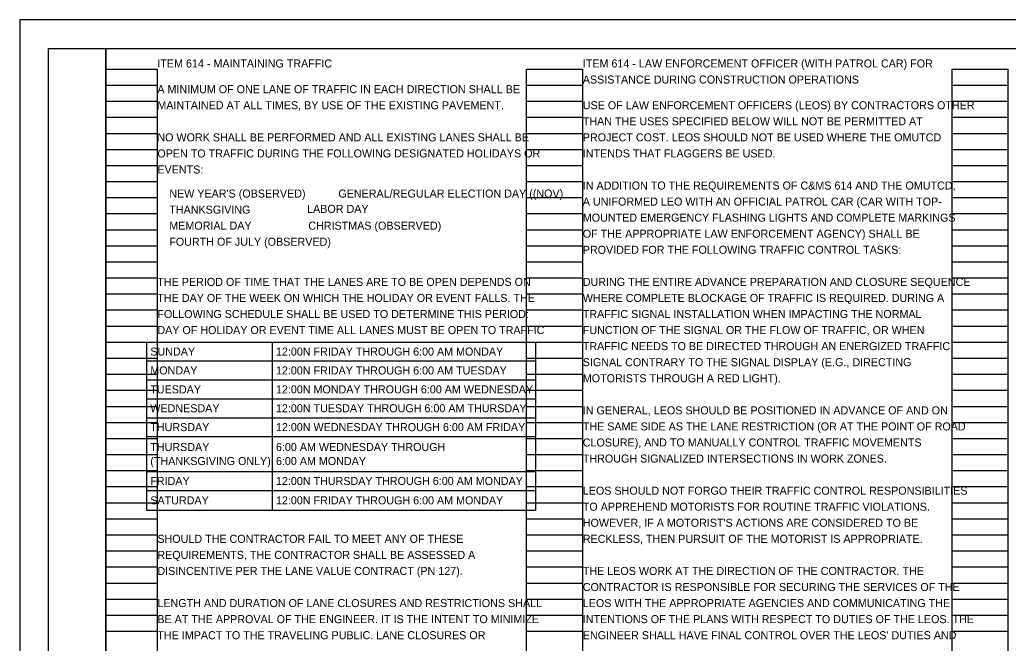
# Model space of a CAD drawing. Extents: x 0 to 34, y 0 to 22.
# Drawn here: x 0 to 17.24, y 11.13 to 22 of the extents above; entities that cross this region are included whole.
import ezdxf

# ---------------------------------------------------------------- set-up
doc = ezdxf.new("R2010")
doc.units = 0
for name, color, linetype in [('SH_Border', 7, 'Continuous'), ('SH_Cut_Line', 7, 'Continuous'), ('SH_Data', 7, 'Continuous'), ('SH_Text', 7, 'Continuous')]:
    doc.layers.add(name, color=color, linetype=linetype)

msp = doc.modelspace()

# ---------------------------------------------------------------- linework, layer by layer
at = {"layer": 'SH_Border'}
for points in [[(0.5, 21.5), (1.5, 21.5), (1.5, 0.5), (0.5, 0.5)], [(1.5, 21.5), (33.5, 21.5), (33.5, 0.5), (1.5, 0.5)]]:
    msp.add_lwpolyline(points, close=True, dxfattribs=at)
at = {"layer": 'SH_Cut_Line'}
msp.add_lwpolyline([(0, 0), (34, 0), (34, 22), (0, 22)], close=True, dxfattribs=at)
at = {"layer": 'SH_Data'}
for p, q in [((1.5, 0.98), (1.5, 21.14)), ((1.5, 21.14), (2.4, 21.14)), ((2.4, 0.98), (2.4, 21.14)), ((8.84, 0.98), (8.84, 21.14)), ((8.84, 21.14), (9.82, 21.14)), ((9.82, 0.98), (9.82, 21.14)), ((16.26, 0.98), (16.26, 21.14)), ((16.26, 21.14), (17.24, 21.14)), ((17.24, 0.98), (17.24, 21.14)), ((1.5, 20.86), (2.4, 20.86)), ((8.84, 20.86), (9.82, 20.86)), ((16.26, 20.86), (17.24, 20.86)), ((1.5, 20.58), (2.4, 20.58)), ((8.84, 20.58), (9.82, 20.58)), ((16.26, 20.58), (17.24, 20.58)), ((1.5, 20.3), (2.4, 20.3)), ((8.84, 20.3), (9.82, 20.3)), ((16.26, 20.3), (17.24, 20.3)), ((1.5, 20.02), (2.4, 20.02)), ((8.84, 20.02), (9.82, 20.02)), ((16.26, 20.02), (17.24, 20.02)), ((1.5, 19.74), (2.4, 19.74)), ((8.84, 19.74), (9.82, 19.74)), ((16.26, 19.74), (17.24, 19.74)), ((1.5, 19.46), (2.4, 19.46)), ((8.84, 19.46), (9.82, 19.46)), ((16.26, 19.46), (17.24, 19.46)), ((1.5, 19.18), (2.4, 19.18)), ((8.84, 19.18), (9.82, 19.18)), ((16.26, 19.18), (17.24, 19.18)), ((1.5, 18.9), (2.4, 18.9)), ((8.84, 18.9), (9.82, 18.9)), ((16.26, 18.9), (17.24, 18.9)), ((1.5, 18.62), (2.4, 18.62)), ((8.84, 18.62), (9.82, 18.62)), ((16.26, 18.62), (17.24, 18.62)), ((1.5, 18.34), (2.4, 18.34)), ((8.84, 18.34), (9.82, 18.34)), ((16.26, 18.34), (17.24, 18.34)), ((1.5, 18.06), (2.4, 18.06)), ((8.84, 18.06), (9.82, 18.06)), ((16.26, 18.06), (17.24, 18.06)), ((1.5, 17.78), (2.4, 17.78)), ((8.84, 17.78), (9.82, 17.78)), ((16.26, 17.78), (17.24, 17.78)), ((1.5, 17.5), (2.4, 17.5)), ((8.84, 17.5), (9.82, 17.5)), ((16.26, 17.5), (17.24, 17.5)), ((1.5, 17.22), (2.4, 17.22)), ((8.84, 17.22), (9.82, 17.22)), ((16.26, 17.22), (17.24, 17.22)), ((1.5, 16.94), (2.4, 16.94)), ((8.84, 16.94), (9.82, 16.94)), ((16.26, 16.94), (17.24, 16.94)), ((1.5, 16.66), (2.4, 16.66)), ((8.84, 16.66), (9.82, 16.66)), ((16.26, 16.66), (17.24, 16.66)), ((1.5, 16.38), (2.4, 16.38)), ((8.84, 16.38), (9.82, 16.38)), ((16.26, 16.38), (17.24, 16.38)), ((1.5, 16.1), (2.4, 16.1)), ((8.84, 16.1), (9.82, 16.1)), ((16.26, 16.1), (17.24, 16.1)), ((1.5, 15.82), (2.4, 15.82)), ((8.84, 15.82), (9.82, 15.82)), ((16.26, 15.82), (17.24, 15.82)), ((1.5, 15.54), (2.4, 15.54)), ((8.84, 15.54), (9.82, 15.54)), ((16.26, 15.54), (17.24, 15.54)), ((1.5, 15.26), (2.4, 15.26)), ((8.84, 15.26), (9.82, 15.26)), ((16.26, 15.26), (17.24, 15.26)), ((1.5, 14.98), (2.4, 14.98)), ((8.84, 14.98), (9.82, 14.98)), ((16.26, 14.98), (17.24, 14.98)), ((1.5, 14.7), (2.4, 14.7)), ((8.84, 14.7), (9.82, 14.7)), ((16.26, 14.7), (17.24, 14.7)), ((1.5, 14.42), (2.4, 14.42)), ((8.84, 14.42), (9.82, 14.42)), ((16.26, 14.42), (17.24, 14.42)), ((1.5, 14.14), (2.4, 14.14)), ((8.84, 14.14), (9.82, 14.14)), ((16.26, 14.14), (17.24, 14.14)), ((1.5, 13.86), (2.4, 13.86)), ((8.84, 13.86), (9.82, 13.86)), ((16.26, 13.86), (17.24, 13.86)), ((1.5, 13.58), (2.4, 13.58)), ((8.84, 13.58), (9.82, 13.58)), ((16.26, 13.58), (17.24, 13.58)), ((1.5, 13.3), (2.4, 13.3)), ((8.84, 13.3), (9.82, 13.3)), ((16.26, 13.3), (17.24, 13.3)), ((1.5, 13.02), (2.4, 13.02)), ((8.84, 13.02), (9.82, 13.02)), ((16.26, 13.02), (17.24, 13.02)), ((1.5, 12.74), (2.4, 12.74)), ((8.84, 12.74), (9.82, 12.74)), ((16.26, 12.74), (17.24, 12.74)), ((1.5, 12.46), (2.4, 12.46)), ((8.84, 12.46), (9.82, 12.46)), ((16.26, 12.46), (17.24, 12.46)), ((1.5, 12.18), (2.4, 12.18)), ((8.84, 12.18), (9.82, 12.18)), ((16.26, 12.18), (17.24, 12.18)), ((1.5, 11.9), (2.4, 11.9)), ((8.84, 11.9), (9.82, 11.9)), ((16.26, 11.9), (17.24, 11.9)), ((1.5, 11.62), (2.4, 11.62)), ((8.84, 11.62), (9.82, 11.62)), ((16.26, 11.62), (17.24, 11.62)), ((1.5, 11.34), (2.4, 11.34)), ((8.84, 11.34), (9.82, 11.34)), ((16.26, 11.34), (17.24, 11.34))]:
    msp.add_line(p, q, dxfattribs=at)
at = {"layer": 'SH_Text'}
for p, q in [((2.211, 16.38), (8.997, 16.38)), ((2.211, 16.38), (2.211, 13.448)), ((4.402, 16.38), (4.402, 13.448)), ((8.997, 16.38), (8.997, 13.448)), ((2.211, 16.051), (8.997, 16.051)), ((2.211, 15.721), (8.997, 15.721)), ((2.211, 15.392), (8.997, 15.392)), ((2.211, 15.062), (8.997, 15.062)), ((2.211, 14.733), (8.997, 14.733)), ((2.211, 14.124), (8.997, 14.124)), ((2.211, 13.794), (8.997, 13.794)), ((2.211, 13.448), (8.997, 13.448))]:
    msp.add_line(p, q, dxfattribs=at)

# ---------------------------------------------------------------- texts
for s, p in [('ITEM 614 - MAINTAINING TRAFFIC', (2.4, 21.168)), ('ITEM 614 - LAW ENFORCEMENT OFFICER (WITH PATROL CAR) FOR ', (9.82, 21.168)), ('A MINIMUM OF ONE LANE OF TRAFFIC IN EACH DIRECTION SHALL BE ', (2.4, 20.72)), ('ASSISTANCE DURING CONSTRUCTION OPERATIONS', (9.82, 20.888)), ('MAINTAINED AT ALL TIMES, BY USE OF THE EXISTING PAVEMENT.', (2.4, 20.44)), ('USE OF LAW ENFORCEMENT OFFICERS (LEOS) BY CONTRACTORS OTHER ', (9.82, 20.44)), ('THAN THE USES SPECIFIED BELOW WILL NOT BE PERMITTED AT ', (9.82, 20.16)), ('NO WORK SHALL BE PERFORMED AND ALL EXISTING LANES SHALL BE ', (2.4, 19.88)), ('PROJECT COST. LEOS SHOULD NOT BE USED WHERE THE OMUTCD ', (9.82, 19.88)), ('OPEN TO TRAFFIC DURING THE FOLLOWING DESIGNATED HOLIDAYS OR ', (2.4, 19.6)), ('INTENDS THAT FLAGGERS BE USED.', (9.82, 19.6)), ('EVENTS:', (2.4, 19.32)), ('IN ADDITION TO THE REQUIREMENTS OF C&MS 614 AND THE OMUTCD, ', (9.82, 19.04)), ("    NEW YEAR'S (OBSERVED)           GENERAL/REGULAR ELECTION DAY ((NOV)", (2.4, 18.9)), ('A UNIFORMED LEO WITH AN OFFICIAL PATROL CAR (CAR WITH TOP-', (9.82, 18.76)), ('    THANKSGIVING', (2.4, 18.62)), ('    LABOR DAY', (4.804, 18.633)), ('MOUNTED EMERGENCY FLASHING LIGHTS AND COMPLETE MARKINGS ', (9.82, 18.48)), ('    MEMORIAL DAY                   CHRISTMAS (OBSERVED)', (2.4, 18.34)), ('OF THE APPROPRIATE LAW ENFORCEMENT AGENCY) SHALL BE ', (9.82, 18.2)), ('    FOURTH OF JULY (OBSERVED) ', (2.4, 18.06)), ('PROVIDED FOR THE FOLLOWING TRAFFIC CONTROL TASKS:', (9.82, 17.92)), ('THE PERIOD OF TIME THAT THE LANES ARE TO BE OPEN DEPENDS ON ', (2.4, 17.36)), ('DURING THE ENTIRE ADVANCE PREPARATION AND CLOSURE SEQUENCE ', (9.82, 17.36)), ('THE DAY OF THE WEEK ON WHICH THE HOLIDAY OR EVENT FALLS. THE ', (2.4, 17.08)), ('WHERE COMPLETE BLOCKAGE OF TRAFFIC IS REQUIRED. DURING A ', (9.82, 17.08)), ('FOLLOWING SCHEDULE SHALL BE USED TO DETERMINE THIS PERIOD:', (2.4, 16.8)), ('TRAFFIC SIGNAL INSTALLATION WHEN IMPACTING THE NORMAL ', (9.82, 16.8)), ('DAY OF HOLIDAY OR EVENT TIME ALL LANES MUST BE OPEN TO TRAFFIC', (2.4, 16.52)), ('FUNCTION OF THE SIGNAL OR THE FLOW OF TRAFFIC, OR WHEN ', (9.82, 16.52)), ('TRAFFIC NEEDS TO BE DIRECTED THROUGH AN ENERGIZED TRAFFIC ', (9.82, 16.24)), ('SUNDAY', (2.277, 16.145)), ('12:00N FRIDAY THROUGH 6:00 AM MONDAY', (4.468, 16.145)), ('SIGNAL CONTRARY TO THE SIGNAL DISPLAY (E.G., DIRECTING ', (9.82, 15.96)), ('MONDAY', (2.277, 15.816)), ('12:00N FRIDAY THROUGH 6:00 AM TUESDAY', (4.468, 15.816)), ('MOTORISTS THROUGH A RED LIGHT).', (9.82, 15.68)), ('TUESDAY', (2.277, 15.486)), ('12:00N MONDAY THROUGH 6:00 AM WEDNESDAY', (4.468, 15.486)), ('WEDNESDAY', (2.277, 15.157)), ('12:00N TUESDAY THROUGH 6:00 AM THURSDAY', (4.468, 15.157)), ('IN GENERAL, LEOS SHOULD BE POSITIONED IN ADVANCE OF AND ON ', (9.82, 15.12)), ('THURSDAY', (2.277, 14.828)), ('12:00N WEDNESDAY THROUGH 6:00 AM FRIDAY', (4.468, 14.828)), ('THE SAME SIDE AS THE LANE RESTRICTION (OR AT THE POINT OF ROAD ', (9.82, 14.84)), ('CLOSURE), AND TO MANUALLY CONTROL TRAFFIC MOVEMENTS ', (9.82, 14.56)), ('THURSDAY', (2.277, 14.481)), ('6:00 AM WEDNESDAY THROUGH', (4.468, 14.481)), ('(THANKSGIVING ONLY)', (2.277, 14.236)), ('6:00 AM MONDAY', (4.468, 14.236)), ('THROUGH SIGNALIZED INTERSECTIONS IN WORK ZONES.', (9.82, 14.28)), ('FRIDAY', (2.277, 13.889)), ('12:00N THURSDAY THROUGH 6:00 AM MONDAY', (4.468, 13.889)), ('LEOS SHOULD NOT FORGO THEIR TRAFFIC CONTROL RESPONSIBILITIES ', (9.82, 13.72)), ('SATURDAY', (2.277, 13.551)), ('12:00N FRIDAY THROUGH 6:00 AM MONDAY', (4.468, 13.551)), ('TO APPREHEND MOTORISTS FOR ROUTINE TRAFFIC VIOLATIONS. ', (9.82, 13.44)), ("HOWEVER, IF A MOTORIST'S ACTIONS ARE CONSIDERED TO BE ", (9.82, 13.16)), ('SHOULD THE CONTRACTOR FAIL TO MEET ANY OF THESE ', (2.4, 12.88)), ('RECKLESS, THEN PURSUIT OF THE MOTORIST IS APPROPRIATE.', (9.82, 12.88)), ('REQUIREMENTS, THE CONTRACTOR SHALL BE ASSESSED A ', (2.4, 12.6)), ('DISINCENTIVE PER THE LANE VALUE CONTRACT (PN 127).', (2.4, 12.32)), ('THE LEOS WORK AT THE DIRECTION OF THE CONTRACTOR. THE ', (9.82, 12.32)), ('CONTRACTOR IS RESPONSIBLE FOR SECURING THE SERVICES OF THE ', (9.82, 12.04)), ('LENGTH AND DURATION OF LANE CLOSURES AND RESTRICTIONS SHALL ', (2.4, 11.76)), ('LEOS WITH THE APPROPRIATE AGENCIES AND COMMUNICATING THE ', (9.82, 11.76)), ('BE AT THE APPROVAL OF THE ENGINEER. IT IS THE INTENT TO MINIMIZE ', (2.4, 11.48)), ('INTENTIONS OF THE PLANS WITH RESPECT TO DUTIES OF THE LEOS. THE ', (9.82, 11.48)), ('THE IMPACT TO THE TRAVELING PUBLIC. LANE CLOSURES OR ', (2.4, 11.2)), ("ENGINEER SHALL HAVE FINAL CONTROL OVER THE LEOS' DUTIES AND ", (9.82, 11.2))]:
    msp.add_text(s, height=0.14, dxfattribs=at).set_placement(p)

doc.saveas('drawing.dxf')
